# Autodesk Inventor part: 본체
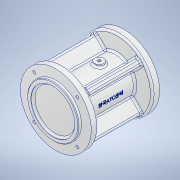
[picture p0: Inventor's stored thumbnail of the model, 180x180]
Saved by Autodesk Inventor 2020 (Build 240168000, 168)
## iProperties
Created: 2024-10
Part Number: 본체
Material: 알루미늄 6061
Document SubType Name: Modeling
Designer: oem
Density: 2.7 g/cm^3
Appearance: 알루미늄 - 평지
Mass: 1179.55 g
Surface Area: 970.929 cm^2
Volume: 436.872 cm^3
Author: oem
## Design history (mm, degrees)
sketch "스케치1"
  geometry: C1 r 58 at (0, 0); 1 further point
  constraints: 1 centre point, 1 coincident
  dimensions: "d0" = 116 diameter of C1
extrude "돌출1" new body sketch "스케치1" distance "d1" = 12; taper "d2" = 0 deg
sketch "스케치2"
  geometry: C1 r 58 at (0, 0) reference; C2 r 30 at (0, 0)
  constraints: 1 centre point, 1 coincident
  dimensions: "d3" = 60 diameter of C2
extrude "돌출2" join sketch "스케치2" distance "d4" = 88; taper "d5" = 0 deg
sketch "스케치3"
  geometry: C1 r 30 at (0, 0) reference; C2 r 58 at (0, 0)
  constraints: 1 centre point, 1 coincident
  dimensions: "d6" = 116 diameter of C2
extrude "돌출3" join sketch "스케치3" distance "d7" = 12; taper "d8" = 0 deg
sketch "스케치4"
  geometry: C1 r 58 at (0, 0) reference; C2 r 42 at (0, 0)
  constraints: 1 centre point, 1 coincident
  dimensions: "d9" = 84 diameter of C2
extrude "돌출4" join sketch "스케치4" distance "d10" = 5; taper "d11" = 0 deg
sketch "스케치5"
  geometry: C1 r 58 at (0, 0) reference; C2 r 42 at (0, 0)
  constraints: 1 centre point, 1 coincident
  dimensions: "d12" = 84 diameter of C2
extrude "돌출5" join sketch "스케치5" distance "d13" = 5; taper "d14" = 0 deg
sketch "스케치7"
  geometry: L1 (58, 12)-(58, 0) reference; L2 (58, 0)-(42, 0) reference; L3 (42, 0)-(42, -5) reference; L4 (42, -5)-(-42, -5) reference; L5 (-42, -5)-(-42, 0) reference; L6 (-42, 0)-(-58, 0) reference; L7 (-58, 0)-(-58, 12) reference; L8 (-58, 12)-(-30, 12) reference; L9 (-30, 12)-(-30, 100) reference; L10 (-30, 100)-(-58, 100) reference; L11 (-58, 100)-(-58, 112) reference; L12 (-58, 112)-(-42, 112) reference; L13 (-42, 112)-(-42, 117) reference; L14 (-42, 117)-(42, 117) reference; L15 (42, 117)-(42, 112) reference; L16 (42, 112)-(58, 112) reference; L17 (58, 112)-(58, 100) reference; L18 (58, 100)-(30, 100) reference; L19 (30, 100)-(30, 12) reference; L20 (30, 12)-(58, 12) reference; L21 (0, 138.748)-(0, -22.97); L22 (30, 100)-(-30, 100) reference; L23 (-30, 100)-(-23, 100); L24 (-30, 100)-(-30, 85); L25 (-30, 12)-(-30, 100) reference; L26 (-30, 85)-(-23, 85); L27 (-23, 85)-(-23, 100); L28 (-23, 85)-(0, 85); L29 (-23, 100)-(0, 100); 1 further point
  constraints: 14 end point, 2 horizontal, 2 point on line, 2 vertical, 1 midpoint
  dimensions: "d24" = 15 distance of L26.end L23.end; "d25" = 46 diameter of L27 L21; "d26" = 30 distance from line of L19 L21.end
revolve "회전1" sketch "스케치7" stored, may be unused: angle "d27" = 90 deg
sketch "스케치8"
  geometry: L1 (0, 0)-(77.91, 0); L2 (0, 0)-(38.184, -38.184); L3 (34.648, -41.719)-(-12.071, 5); L4 (41.719, -34.648)-(-5, 12.071); L5 (34.648, -41.719)-(41.719, -34.648); L6 (-12.071, 5)-(-5, 12.071); C1 r 23 at (0, 0) reference; C2 r 58 at (0, 0) reference
  constraints: 12 end point, 1 horizontal
  dimensions: "d28" = 45 deg angle of L1 L2; "d29" = 54 distance of L1.start L2.end; "d30" = 5 distance between parallel lines of L2 L3; "d31" = 5 distance between parallel lines of L2 L4
extrude "돌출7" join sketch "스케치8" stored distance "d32" = 5; taper "d33" = 0 deg
sketch "스케치9"
  geometry: L1 (42, 117)-(42, 112) reference; L2 (42, 112)-(58, 112) reference; L3 (58, 112)-(58, 100) reference; L4 (58, 100)-(23, 100) reference; L5 (23, 100)-(23, 85) reference; L6 (23, 85)-(30, 85) reference; L7 (30, 85)-(30, 12) reference; L8 (30, 12)-(58, 12) reference; L9 (58, 12)-(58, 0) reference; L10 (58, 0)-(42, 0) reference; L11 (42, 0)-(42, -5) reference; L12 (42, -5)-(-42, -5) reference; L13 (-42, -5)-(-42, 0) reference; L14 (-42, 0)-(-58, 0) reference; L15 (-58, 0)-(-58, 12) reference; L16 (-58, 12)-(-30, 12) reference; L17 (-30, 12)-(-30, 85) reference; L18 (-30, 85)-(-23, 85) reference; L19 (-23, 85)-(-23, 100) reference; L20 (-23, 100)-(-58, 100) reference; L21 (-58, 100)-(-58, 112) reference; L22 (-58, 112)-(-42, 112) reference; L23 (-42, 112)-(-42, 117) reference; L24 (-42, 117)-(42, 117) reference; C1 r 7.5 at (0, 41); 1 further point
  constraints: 1 centre point, 1 vertical alignment
  dimensions: "d37" = 15 diameter of C1; "d38" = 29 distance from line of L16 C1.centre
extrude "돌출8" join sketch "스케치9" stored distance "d39" = 68; taper "d40" = 0 deg
sketch "스케치11"
  geometry: C1 r 42 at (0, 0) reference; 2 further points
  constraints: 1 coincident
hole "구멍1" sketch "스케치11" at (0, 0) diameter "d41" = 72; stored, may be unused: countersink angle "d45" = 90 deg, drill point angle "d47" = 0 deg; dims "d42" = 6, "d43" = 4, "d44" = 2, "d46" = 3
sketch "스케치12"
  geometry: L1 (-42, 112)-(-42, 117) reference; L2 (-42, 117)-(42, 117) reference; L3 (42, 117)-(42, 112) reference; L4 (42, 112)-(58, 112) reference; L5 (58, 112)-(58, 100) reference; L6 (58, 100)-(23, 100) reference; L7 (23, 100)-(23, 85) reference; L8 (23, 85)-(30, 85) reference; L9 (30, 85)-(30, 48.5) reference; L10 (30, 48.5)-(34, 48.5) reference; L11 (34, 48.5)-(34, 33.5) reference; L12 (34, 33.5)-(30, 33.5) reference; L13 (30, 33.5)-(30, 12) reference; L14 (30, 12)-(58, 12) reference; L15 (58, 12)-(58, 0) reference; L16 (58, 0)-(42, 0) reference; L17 (42, 0)-(42, -5) reference; L18 (42, -5)-(36, -5) reference; L19 (36, -5)-(36, -2) reference; L20 (36, -2)-(-36, -2) reference; L21 (-36, -2)-(-36, -5) reference; L22 (-36, -5)-(-42, -5) reference; L23 (-42, -5)-(-42, 0) reference; L24 (-42, 0)-(-58, 0) reference; L25 (-58, 0)-(-58, 12) reference; L26 (-58, 12)-(-30, 12) reference; L27 (-30, 12)-(-30, 33.5) reference; L28 (-30, 33.5)-(-34, 33.5) reference; L29 (-34, 33.5)-(-34, 48.5) reference; L30 (-34, 48.5)-(-30, 48.5) reference; L31 (-30, 48.5)-(-30, 85) reference; L32 (-30, 85)-(-23, 85) reference; L33 (-23, 85)-(-23, 100) reference; L34 (-23, 100)-(-58, 100) reference; L35 (-58, 100)-(-58, 112) reference; L36 (-58, 112)-(-42, 112) reference; L37 (36, -5)-(-36, -5) reference; L38 (0, -5)-(0, 117); L39 (42, 117)-(-42, 117) reference; L40 (-36, -2)-(36, -2) reference; L41 (0, -2)-(21, -2); L42 (21, -2)-(21, 14); L43 (21, 14)-(25, 14); L44 (25, 14)-(25, 68); L45 (24.452, 12)-(24.452, 85) reference; L46 (25, 68)-(21, 68); L47 (21, 68)-(21, 80); L48 (21, 80)-(18, 80); L49 (18, 80)-(18, 98); L50 (18, 98)-(16, 98); L51 (16, 98)-(16, 102); L52 (16, 102)-(10.5, 102); L53 (10.5, 102)-(10.5, 105); L54 (10.5, 105)-(0, 105); 4 further points
  constraints: 28 end point, 9 perpendicular, 4 point on line, 3 midpoint, 1 parallel, 1 vertical
  dimensions: "d48" = 21 diameter of L53 L38; "d49" = 32 diameter of L51 L38; "d50" = 36 diameter of L49 L38; "d51" = 42 diameter of L47 L38; "d53" = 3 distance of L52.end L53.end; "d54" = 4 distance of L50.end L51.end; "d57" = 18 distance of L48.end L49.end; "d58" = 82 distance between parallel lines of L20 L48; "d59" = 54 distance between parallel lines of L43 L46; "d60" = 16 distance between parallel lines of L41 L43; "d153" = 50 diameter of L44 L38
revolve "회전2" sketch "스케치12" stored, may be unused: angle "d61" = 90 deg
sketch "스케치13"
  geometry: C1 r 42 at (0, 0) reference; 2 further points
  constraints: 1 coincident
hole "구멍2" sketch "스케치13" at (0, 0) diameter "d62" = 72; stored, may be unused: countersink angle "d66" = 90 deg, drill point angle "d68" = 0 deg; dims "d63" = 6, "d64" = 4, "d65" = 2, "d67" = 4
sketch "스케치14"
  geometry: C1 r 7.5 at (0, 0) reference; 2 further points
  constraints: 1 coincident
hole "구멍3" sketch "스케치14" at (0, 0) diameter "d69" = 5.1881; stored, may be unused: countersink angle "d73" = 90 deg, drill point angle "d75" = 0 deg; dims "d70" = 12, "d71" = 4, "d72" = 2, "d74" = 16
sketch "스케치16" dims "d88" = 56
  geometry: L1 (0, 0)-(0, -28); C1 r 21 at (0, 0) reference; C2 r 36 at (0, 0) reference; 4 further points
  constraints: 2 coincident, 2 end point, 1 vertical, 1 vertical alignment, 7 other
  dimensions: "d91" = 360 deg dimension on C1.centre point (0, -28) (derived)
hole "구멍5" sketch "스케치16" at (0, -28), (28, 0), (0, 28), (-28, 0) diameter "d93" = 4.134; stored, may be unused: countersink angle "d97" = 90 deg, drill point angle "d99" = 118 deg; dims "d94" = 10, "d95" = 4, "d96" = 2, "d98" = 12
sketch "스케치18"
  geometry: L1 (0, 0)-(0, -50); L2 (0, 0)-(-35.355, -35.355); C1 r 42 at (0, 0) reference; C2 r 58 at (0, 0) reference; C3 r 10.5 at (0, 0) reference; A1 r 50 centre (0, 0) between (0, -50) and (-35.355, -35.355); 4 further points
  constraints: 4 end point, 2 coincident, 2 point on circle, 1 centre point, 1 vertical, 5 other
  dimensions: "d112" = 100 diameter of A1; "d113" = 45 deg angle of L2 L1; "d116" = 360 deg dimension on C1.centre point (-35.355, -35.355) (derived)
hole "구멍7" sketch "스케치18" at (-35.355, -35.355), (35.355, -35.355), (35.355, 35.355), (-35.355, 35.355) diameter "d118" = 4.917; stored, may be unused: countersink angle "d122" = 90 deg, drill point angle "d124" = 118 deg; dims "d119" = 12, "d120" = 4, "d121" = 2, "d123" = 14
node "작업 평면1"
node "작업 평면2"
sketch "스케치19"
  geometry: L1 (3.002, 72.739)-(3.002, 31.261); L2 (3.002, 31.261)-(-3.002, 31.261); L3 (-3.002, 31.261)-(-3.002, 72.739); L4 (-3.002, 72.739)-(3.002, 72.739); L5 (3.002, 52)-(-3.002, 52); L6 (58, 0)-(-58, 0) reference; 2 further points
  constraints: 3 midpoint, 2 end point, 1 vertical alignment, 2 other
  dimensions: "d126" = 52 distance from line of L6 L5.end
feature "엠보싱1" sketch "스케치19" dims "d0" = 116, "d127" = 0.5, "d128" = 0
fillet "모깎기1" dims "d129" = 3
chamfer "모따기1" distance "d130" = 1; stored, may be unused: second distance "d131" = 2, angle "d132" = 45 deg
fillet "모깎기2" dims "d133" = 3
fillet "모깎기3" dims "d134" = 3
fillet "모깎기4" dims "d135" = 3
fillet "모깎기5" dims "d136" = 3
fillet "모깎기6" dims "d137" = 3
fillet "모깎기7" dims "d138" = 3
fillet "모깎기8" dims "d139" = 3
fillet "모깎기10" dims "d141" = 3
fillet "모깎기11" dims "d142" = 0.6
chamfer "모따기2" distance "d143" = 1; stored, may be unused: second distance "d144" = 2, angle "d145" = 45 deg
fillet "모깎기12" dims "d146" = 0.6
fillet "모깎기13" dims "d147" = 3
chamfer "모따기3" distance "d148" = 1; stored, may be unused: second distance "d149" = 2, angle "d150" = 45 deg
fillet "모깎기14" dims "d151" = 3
fillet "모깎기15" dims "d152" = 3
node "솔리드1"
pattern_circular "원형 패턴2" dims angle "d35" = 360 deg
mirror "미러1"
node "절단 모서리 투영2"
node "절단 모서리 투영3"
node "절단 모서리 투영4"
node "절단 모서리 투영6"
feature "A9D066F2-1C7D-4E18-AEED-F7BC21143FA4" dims "d41" = 72, "d42" = 6, "d43" = 4, "d44" = 2, "d45" = 90 deg, "d46" = 3, "d47" = 0
